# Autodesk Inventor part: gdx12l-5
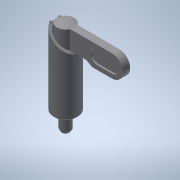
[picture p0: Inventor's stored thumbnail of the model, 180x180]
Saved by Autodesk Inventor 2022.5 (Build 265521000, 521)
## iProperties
Created: 2016-12
Part Number: gdx12l-5
Material: 一般
Document SubType Name: Modeling
Designer: imaocorp
Density: 1 g/cm^3
Appearance: 既定
Author: imaocorp
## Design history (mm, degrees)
node "gdx12l-5.x_t1"
node "gdx12l-5"
node "Base1"
